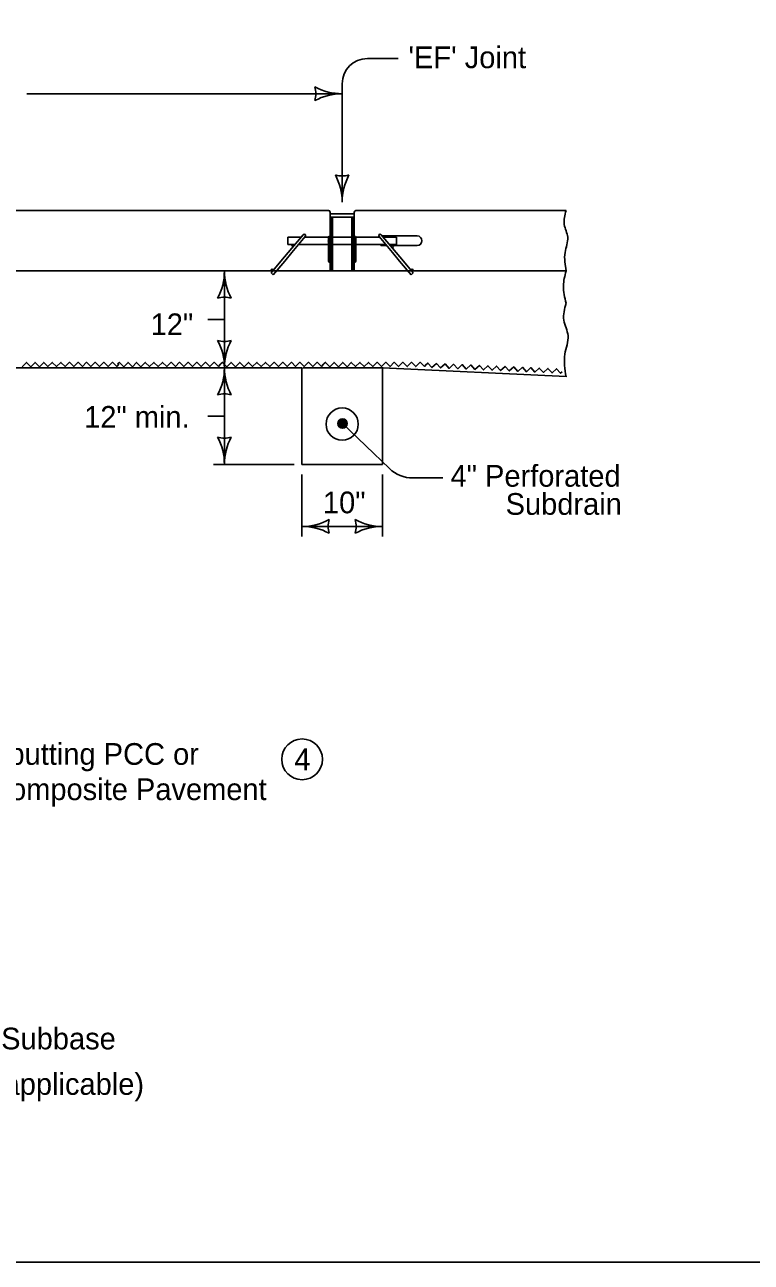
# Model space of a CAD drawing. Extents: x 5546 to 81668, y 3174 to 15999.
# Drawn here: x 15194 to 15729, y 7924 to 8836 of the extents above; entities that cross this region are included whole.
import ezdxf

# ---------------------------------------------------------------- set-up
doc = ezdxf.new("R2010")
doc.units = 0
for name, color, linetype in [('Level 61', 7, 'Continuous'), ('PS_BOLT', 7, 'Continuous'), ('PS_CONST', 7, 'Continuous'), ('PS_DAWA', 7, 'Continuous'), ('PS_DIM', 7, 'Continuous'), ('PS_SHAPE', 7, 'Continuous'), ('PS_TEXT', 7, 'Continuous')]:
    doc.layers.add(name, color=color, linetype=linetype)

msp = doc.modelspace()

# ---------------------------------------------------------------- linework, layer by layer
at = {"layer": 'Level 61'}
msp.add_lwpolyline([(13732.52, 9944.02), (16867.53, 9944.02), (16867.53, 7924.02), (13732.52, 7924.02)], close=True, dxfattribs=at)
at = {"layer": 'PS_BOLT'}
for p, q in [((15417.71, 8699.17), (14866.72, 8699.17)), ((15418.96, 8697.92), (15418.96, 8697.92)), ((15418.96, 8654.62), (15418.96, 8697.92)), ((14866.72, 8654.62), (15305.81, 8654.62)), ((15305.81, 8654.62), (15418.96, 8654.62))]:
    msp.add_line(p, q, dxfattribs=at)
msp.add_lwpolyline([(15418.96, 8697.92), (15418.62, 8698.92), (15417.71, 8699.17)], dxfattribs=at)
at = {"layer": 'PS_CONST'}
for p, q in [((15469.22, 8811.23), (15446.43, 8811.23)), ((15427.87, 8737.7), (15427.87, 8792.66)), ((15427.87, 8705.31), (15427.87, 8737.7)), ((15341.13, 8654.62), (15341.13, 8583.34)), ((15341.13, 8618.98), (15329.01, 8618.98)), ((15341.13, 8583.34), (15341.13, 8512.06)), ((15341.13, 8547.7), (15329.01, 8547.7)), ((15427.82, 8542.44), (15462.64, 8509.02)), ((15392.59, 8512.06), (15333.02, 8512.06)), ((15398.17, 8504.63), (15398.17, 8458.91)), ((15457.57, 8504.63), (15457.57, 8458.91)), ((15502.03, 8502.06), (15479.96, 8502.06)), ((15457.57, 8466.33), (15398.17, 8466.33))]:
    msp.add_line(p, q, dxfattribs=at)
msp.add_lwpolyline([(15428.45, 8538.98), (15427.28, 8539.51), (15425.46, 8540.07), (15425.11, 8541.91), (15425.36, 8543.53), (15426.52, 8545.03), (15428.25, 8544.88), (15430.08, 8544.62), (15430.95, 8543.17), (15431.11, 8541.64), (15430.03, 8539.63), (15428.7, 8539.46), (15426.88, 8539.93), (15425.39, 8541.09), (15425.44, 8542.82), (15426.6, 8544.21), (15428.24, 8544.37), (15430.06, 8544.01), (15430.33, 8542.98), (15430.71, 8541.75), (15429.85, 8540.24), (15428.52, 8540.28), (15427, 8540.53), (15425.91, 8541.38), (15426.46, 8542.89), (15427.61, 8543.78), (15429.14, 8543.83), (15429.52, 8543.01), (15430, 8542.08), (15429.26, 8540.88), (15428.12, 8540.6), (15427.12, 8541.14), (15427.05, 8542.26), (15427.59, 8543.06), (15428.62, 8543.34), (15429.11, 8542.92), (15429.4, 8542.29), (15428.86, 8541.4), (15428.14, 8541.21), (15427.44, 8541.64), (15427.56, 8542.25), (15428.08, 8542.64), (15428.8, 8542.62), (15428.78, 8542.11), (15428.16, 8541.82)], dxfattribs=at)
msp.add_circle((15428.18, 8542.16), 3.47, dxfattribs=at)
for centre, radius, start, end in [((15446.43, 8792.67), 18.56, 90, 180), ((15427.87, 8741.16), 16.51, 252.26665, 287.73335), ((15385.12, 8705.31), 42.75, 0, 28.07249), ((15470.62, 8705.31), 42.75, 151.92751, 180), ((15298.38, 8654.62), 42.75, 331.92751, 0), ((15383.88, 8654.62), 42.75, 180, 208.07249), ((15341.13, 8618.78), 16.51, 72.26665, 107.73335), ((15341.13, 8619.18), 16.51, 252.26665, 287.73335), ((15298.38, 8583.34), 42.75, 0, 28.07249), ((15383.88, 8583.34), 42.75, 151.92751, 180), ((15298.38, 8583.34), 42.75, 331.92751, 0), ((15383.88, 8583.34), 42.75, 180, 208.07249), ((15341.13, 8547.5), 16.51, 72.26665, 107.73335), ((15341.13, 8547.9), 16.51, 252.26665, 287.73335), ((15298.38, 8512.06), 42.75, 0, 28.07249), ((15383.88, 8512.06), 42.75, 151.92751, 180), ((15479.96, 8527.06), 25, 226.17392, 270), ((15398.17, 8509.08), 42.75, 270, 298.07249), ((15398.17, 8423.58), 42.75, 61.92751, 90), ((15434.01, 8466.33), 16.51, 162.26665, 197.73335), ((15421.73, 8466.33), 16.51, 342.26665, 17.73335), ((15457.57, 8509.08), 42.75, 241.92751, 270), ((15457.57, 8423.58), 42.75, 90, 118.07249)]:
    msp.add_arc(centre, radius, start, end, dxfattribs=at)
at = {"layer": 'PS_DAWA'}
msp.add_line((15427.87, 8785.23), (15195.61, 8785.23), dxfattribs=at)
for centre, radius, start, end in [((15392.02, 8785.24), 16.51, 342.26665, 17.73335), ((15427.87, 8827.99), 42.75, 241.92751, 270), ((15392.02, 8785.24), 16.51, 342.26665, 17.73335), ((15427.87, 8827.99), 42.75, 241.92751, 270), ((15427.87, 8742.49), 42.75, 90, 118.07249), ((15427.87, 8742.49), 42.75, 90, 118.07249)]:
    msp.add_arc(centre, radius, start, end, dxfattribs=at)
at = {"layer": 'PS_DIM'}
for p, q in [((15436.78, 8679.61), (15436.78, 8697.93)), ((15438.02, 8699.17), (15592.87, 8699.17)), ((15437.85, 8661.75), (15437.85, 8679.57)), ((15436.78, 8654.62), (15436.78, 8661.71)), ((15476.31, 8654.62), (15436.78, 8654.62)), ((15592.87, 8654.62), (15476.31, 8654.62))]:
    msp.add_line(p, q, dxfattribs=at)
for centre, radius, start, end in [((15438.02, 8697.93), 1.25, 90, 180), ((15437.31, 8679.57), 0.535, 0, 176.27485), ((15437.31, 8661.75), 0.535, 184.7481, 0)]:
    msp.add_arc(centre, radius, start, end, dxfattribs=at)
msp.add_spline([(15592.87, 8699.17), (15591.51, 8688.88), (15594.08, 8679.51), (15592.12, 8668.32), (15592.87, 8654.62)], degree=3, dxfattribs=at)
at = {"layer": 'PS_SHAPE'}
for p, q in [((15417.71, 8699.17), (14310.64, 8699.17)), ((15418.96, 8668.16), (15418.96, 8697.92)), ((15436.78, 8696.76), (15418.96, 8696.76)), ((15420.74, 8694.36), (15418.96, 8694.36)), ((15419.14, 8694.36), (15419.14, 8668.16)), ((15419.32, 8694.36), (15419.32, 8668.16)), ((15419.49, 8694.36), (15419.49, 8668.16)), ((15419.67, 8694.36), (15419.67, 8668.16)), ((15419.85, 8694.36), (15419.85, 8668.16)), ((15420.03, 8694.36), (15420.03, 8668.16)), ((15420.21, 8694.36), (15420.21, 8668.16)), ((15420.38, 8694.36), (15420.38, 8668.16)), ((15420.56, 8694.36), (15420.56, 8668.16)), ((15420.74, 8694.36), (15420.74, 8679.57)), ((15420.74, 8694.36), (15435, 8694.36)), ((15420.74, 8679.57), (15420.74, 8694.36)), ((15435, 8694.36), (15435, 8679.57)), ((15435, 8694.36), (15435, 8679.57)), ((15436.78, 8694.36), (15435, 8694.36)), ((15435.18, 8694.36), (15435.18, 8668.16)), ((15435.35, 8694.36), (15435.35, 8668.16)), ((15435.53, 8694.36), (15435.53, 8668.16)), ((15435.71, 8694.36), (15435.71, 8668.16)), ((15435.89, 8694.36), (15435.89, 8668.16)), ((15436.07, 8694.36), (15436.07, 8668.16)), ((15436.24, 8694.36), (15436.24, 8668.16)), ((15436.42, 8694.36), (15436.42, 8668.16)), ((15436.6, 8694.36), (15436.6, 8668.16)), ((15436.78, 8668.16), (15436.78, 8697.92)), ((15592.87, 8699.17), (15438.03, 8699.17)), ((15387.77, 8674.22), (15387.77, 8679.57)), ((15397.58, 8679.57), (15387.77, 8679.57)), ((15393.09, 8674.22), (15387.77, 8674.22)), ((15399.05, 8681.32), (15388.01, 8668.16)), ((15390.8, 8668.16), (15400.69, 8679.95)), ((15417.89, 8674.22), (15395.88, 8674.22)), ((15397.58, 8679.57), (15397.58, 8679.57)), ((15417.89, 8679.57), (15400.37, 8679.57)), ((15417.89, 8661.75), (15417.89, 8679.57)), ((15417.89, 8678.86), (15417.89, 8678.86)), ((15420.74, 8679.57), (15420.74, 8674.22)), ((15435, 8679.57), (15420.74, 8679.57)), ((15435, 8674.22), (15420.74, 8674.22)), ((15420.74, 8674.22), (15420.74, 8668.16)), ((15435, 8679.57), (15435, 8674.22)), ((15435, 8674.22), (15435, 8668.16)), ((15437.31, 8680.1), (15437.31, 8680.1)), ((15437.85, 8661.75), (15437.85, 8679.57)), ((15455.37, 8679.57), (15437.85, 8679.57)), ((15459.86, 8674.22), (15437.85, 8674.22)), ((15464.94, 8668.16), (15455.05, 8679.95)), ((15456.38, 8674.22), (15456.38, 8673.33)), ((15456.69, 8681.32), (15467.73, 8668.16)), ((15483.11, 8680.46), (15457.41, 8680.46)), ((15458.16, 8679.57), (15458.16, 8679.57)), ((15467.96, 8679.57), (15458.16, 8679.57)), ((15467.96, 8674.22), (15462.65, 8674.22)), ((15467.96, 8674.22), (15467.96, 8679.57)), ((15388.01, 8668.16), (15382.75, 8661.89)), ((15390.8, 8668.16), (15385.54, 8661.89)), ((15418.96, 8661.89), (15418.96, 8668.16)), ((15419.14, 8668.16), (15419.14, 8661.89)), ((15419.32, 8668.16), (15419.32, 8661.89)), ((15419.49, 8668.16), (15419.49, 8661.89)), ((15419.67, 8668.16), (15419.67, 8661.89)), ((15419.85, 8668.16), (15419.85, 8661.89)), ((15420.03, 8668.16), (15420.03, 8661.89)), ((15420.21, 8668.16), (15420.21, 8661.89)), ((15420.38, 8668.16), (15420.38, 8661.89)), ((15420.56, 8668.16), (15420.56, 8661.89)), ((15420.74, 8668.16), (15420.74, 8661.89)), ((15435, 8668.16), (15435, 8661.89)), ((15435.18, 8668.16), (15435.18, 8661.89)), ((15435.35, 8668.16), (15435.35, 8661.89)), ((15435.53, 8668.16), (15435.53, 8661.89)), ((15435.71, 8668.16), (15435.71, 8661.89)), ((15435.89, 8668.16), (15435.89, 8661.89)), ((15436.07, 8668.16), (15436.07, 8661.89)), ((15436.24, 8668.16), (15436.24, 8661.89)), ((15436.42, 8668.16), (15436.42, 8661.89)), ((15436.6, 8668.16), (15436.6, 8661.89)), ((15436.78, 8661.89), (15436.78, 8668.16)), ((15460.6, 8673.33), (15456.38, 8673.33)), ((15483.11, 8673.33), (15463.4, 8673.33)), ((15464.94, 8668.16), (15470.2, 8661.89)), ((15467.73, 8668.16), (15472.99, 8661.89)), ((15382.75, 8661.89), (15375.5, 8653.26)), ((15385.54, 8661.89), (15377.14, 8651.89)), ((15418.96, 8654.62), (15418.96, 8661.89)), ((15419.14, 8661.89), (15419.14, 8654.62)), ((15419.32, 8661.89), (15419.32, 8654.62)), ((15419.49, 8661.89), (15419.49, 8654.62)), ((15419.67, 8661.89), (15419.67, 8654.62)), ((15419.85, 8661.89), (15419.85, 8654.62)), ((15420.03, 8661.89), (15420.03, 8654.62)), ((15420.21, 8661.89), (15420.21, 8654.62)), ((15420.38, 8661.89), (15420.38, 8654.62)), ((15420.56, 8661.89), (15420.56, 8654.62)), ((15420.74, 8661.89), (15420.74, 8654.62)), ((15435, 8661.89), (15435, 8654.62)), ((15435.18, 8661.89), (15435.18, 8654.62)), ((15435.35, 8661.89), (15435.35, 8654.62)), ((15435.53, 8661.89), (15435.53, 8654.62)), ((15435.71, 8661.89), (15435.71, 8654.62)), ((15435.89, 8661.89), (15435.89, 8654.62)), ((15436.07, 8661.89), (15436.07, 8654.62)), ((15436.24, 8661.89), (15436.24, 8654.62)), ((15436.42, 8661.89), (15436.42, 8654.62)), ((15436.6, 8661.89), (15436.6, 8654.62)), ((15436.78, 8654.62), (15436.78, 8661.89)), ((15437.85, 8661.75), (15437.85, 8661.75)), ((15470.2, 8661.89), (15478.6, 8651.89)), ((15472.99, 8661.89), (15480.24, 8653.26)), ((15376.64, 8654.62), (14310.64, 8654.62)), ((15377.14, 8651.89), (15375.5, 8653.26)), ((15420.74, 8654.62), (15379.43, 8654.62)), ((15435, 8654.62), (15420.74, 8654.62)), ((15476.31, 8654.62), (15435, 8654.62)), ((15478.6, 8651.89), (15480.24, 8653.26)), ((15592.87, 8654.62), (15479.1, 8654.62)), ((15398.17, 8583.34), (14310.64, 8583.34)), ((15398.17, 8512.06), (15398.17, 8583.34)), ((15458.19, 8583.34), (15398.79, 8583.34)), ((15457.57, 8512.06), (15457.57, 8583.34)), ((15457.57, 8583.34), (15592.87, 8576.78)), ((15457.57, 8512.06), (15398.17, 8512.06))]:
    msp.add_line(p, q, dxfattribs=at)
for points in [[(15435, 8694.22), (15434.85, 8694.36)], [(15435, 8673.93), (15434.7, 8674.22)], [(15263.38, 8585.83), (15261.8, 8584.23), (15258.62, 8587.39), (15255.46, 8584.22), (15252.28, 8587.38), (15249.12, 8584.19), (15245.95, 8587.36), (15242.79, 8584.18), (15239.61, 8587.34), (15236.46, 8584.16), (15233.27, 8587.33), (15230.11, 8584.15), (15226.94, 8587.31), (15223.78, 8584.13), (15220.6, 8587.29), (15217.44, 8584.12), (15214.27, 8587.28), (15211.11, 8584.1), (15207.94, 8587.26), (15204.78, 8584.08), (15201.59, 8587.24), (15198.44, 8584.07), (15195.27, 8587.23), (15192.1, 8584.04)], [(15338.22, 8585.83), (15336.64, 8584.23), (15333.46, 8587.39), (15330.31, 8584.22), (15327.12, 8587.38), (15323.96, 8584.19), (15320.8, 8587.36), (15317.64, 8584.18), (15314.45, 8587.34), (15311.3, 8584.16), (15308.12, 8587.33), (15304.96, 8584.15), (15301.78, 8587.31), (15298.63, 8584.13), (15295.44, 8587.29), (15292.28, 8584.12), (15289.12, 8587.28), (15285.96, 8584.1), (15282.78, 8587.26), (15279.62, 8584.08), (15276.44, 8587.24), (15273.28, 8584.07), (15270.11, 8587.23), (15266.95, 8584.04), (15263.77, 8587.21), (15262.35, 8586.08)], [(15414.19, 8585.83), (15412.61, 8584.23), (15409.43, 8587.39), (15406.28, 8584.22), (15403.09, 8587.38), (15399.93, 8584.19), (15396.77, 8587.36), (15393.6, 8584.18), (15390.42, 8587.34), (15387.27, 8584.16), (15384.09, 8587.33), (15380.93, 8584.15), (15377.75, 8587.31), (15374.6, 8584.13), (15371.41, 8587.29), (15368.25, 8584.12), (15365.09, 8587.28), (15361.92, 8584.1), (15358.75, 8587.26), (15355.59, 8584.08), (15352.41, 8587.24), (15349.25, 8584.07), (15346.08, 8587.23), (15342.92, 8584.04), (15339.74, 8587.21), (15338.32, 8586.08)], [(15490.06, 8585.83), (15488.48, 8584.23), (15485.3, 8587.39), (15482.15, 8584.22), (15478.96, 8587.38), (15475.8, 8584.19), (15472.63, 8587.36), (15469.47, 8584.18), (15466.29, 8587.34), (15463.14, 8584.16), (15459.95, 8587.33), (15456.79, 8584.15), (15453.62, 8587.31), (15450.47, 8584.13), (15447.28, 8587.29), (15444.12, 8584.12), (15440.95, 8587.28), (15437.79, 8584.1), (15434.62, 8587.26), (15431.46, 8584.08), (15428.27, 8587.24), (15425.12, 8584.07), (15421.95, 8587.23), (15418.79, 8584.04), (15415.61, 8587.21), (15414.18, 8586.08)], [(15565.3, 8581.9), (15563.65, 8580.38), (15560.63, 8583.68), (15557.33, 8580.65), (15554.29, 8583.96), (15551, 8580.93), (15547.96, 8584.23), (15544.66, 8581.21), (15541.64, 8584.5), (15538.33, 8581.48), (15535.3, 8584.78), (15532.01, 8581.75), (15528.98, 8585.06), (15525.67, 8582.02), (15522.64, 8585.33), (15519.35, 8582.3), (15516.32, 8585.6), (15513.01, 8582.57), (15509.99, 8585.87), (15506.69, 8582.84), (15503.65, 8586.15), (15500.36, 8583.12), (15497.32, 8586.42), (15494.02, 8583.39), (15491, 8586.69), (15489.35, 8585.18)], [(15589.98, 8580.33), (15588.82, 8579.26), (15585.79, 8582.57), (15582.49, 8579.53), (15579.45, 8582.84), (15576.16, 8579.82), (15573.12, 8583.11), (15569.82, 8580.09), (15566.8, 8583.38), (15565.15, 8581.88)]]:
    msp.add_lwpolyline(points, dxfattribs=at)
for centre, radius in [((15391.56, 8673.51), 0.713), ((15464.92, 8672.62), 0.713), ((15376.31, 8655.33), 0.713), ((15479.43, 8655.33), 0.713), ((15427.87, 8541.76), 11.88)]:
    msp.add_circle(centre, radius, dxfattribs=at)
for centre, radius, start, end in [((15417.71, 8697.92), 1.25, 0, 90), ((15438.03, 8697.92), 1.25, 90, 180), ((15399.87, 8680.64), 1.07, 320.00367, 139.99636), ((15418.42, 8679.57), 0.535, 0, 180), ((15437.31, 8679.57), 0.535, 0, 180), ((15455.87, 8680.64), 1.07, 40.00364, 219.99633), ((15483.11, 8676.9), 3.56, 270, 90), ((15418.42, 8661.75), 0.535, 180, 0), ((15437.31, 8661.75), 0.535, 180, 0)]:
    msp.add_arc(centre, radius, start, end, dxfattribs=at)
for points in [[(15592.87, 8699.17), (15591.51, 8688.87), (15594.08, 8679.5), (15592.12, 8668.31), (15592.87, 8654.62)], [(15417.89, 8679.21), (15417.79, 8679.2), (15417.71, 8679.22), (15417.63, 8679.2), (15417.57, 8679.22), (15417.51, 8679.2), (15417.45, 8679.21)], [(15417.89, 8678.86), (15417.79, 8678.85), (15417.71, 8678.86), (15417.63, 8678.85), (15417.57, 8678.86), (15417.51, 8678.84), (15417.45, 8678.85)], [(15417.89, 8678.5), (15417.79, 8678.49), (15417.71, 8678.5), (15417.63, 8678.49), (15417.57, 8678.51), (15417.51, 8678.49), (15417.45, 8678.5)], [(15417.89, 8678.14), (15417.79, 8678.14), (15417.71, 8678.15), (15417.63, 8678.14), (15417.57, 8678.15), (15417.51, 8678.13), (15417.45, 8678.14)], [(15417.89, 8677.79), (15417.79, 8677.78), (15417.71, 8677.79), (15417.63, 8677.78), (15417.57, 8677.79), (15417.51, 8677.77), (15417.45, 8677.78)], [(15417.89, 8677.43), (15417.79, 8677.42), (15417.71, 8677.43), (15417.63, 8677.42), (15417.57, 8677.44), (15417.51, 8677.42), (15417.45, 8677.43)], [(15417.89, 8677.07), (15417.79, 8677.07), (15417.71, 8677.08), (15417.63, 8677.07), (15417.57, 8677.08), (15417.51, 8677.06), (15417.45, 8677.07)], [(15417.89, 8676.72), (15417.79, 8676.71), (15417.71, 8676.72), (15417.63, 8676.71), (15417.57, 8676.73), (15417.51, 8676.71), (15417.45, 8676.71)], [(15417.89, 8676.36), (15417.79, 8676.35), (15417.71, 8676.37), (15417.63, 8676.35), (15417.57, 8676.37), (15417.51, 8676.35), (15417.45, 8676.36)], [(15417.89, 8676), (15417.79, 8676), (15417.71, 8676.01), (15417.63, 8676), (15417.57, 8676.01), (15417.51, 8675.99), (15417.45, 8676)], [(15417.89, 8675.65), (15417.79, 8675.64), (15417.71, 8675.65), (15417.63, 8675.64), (15417.57, 8675.66), (15417.51, 8675.64), (15417.45, 8675.64)], [(15417.89, 8675.29), (15417.79, 8675.28), (15417.71, 8675.3), (15417.63, 8675.28), (15417.57, 8675.3), (15417.51, 8675.28), (15417.45, 8675.29)], [(15417.89, 8674.94), (15417.79, 8674.93), (15417.71, 8674.94), (15417.63, 8674.93), (15417.57, 8674.94), (15417.51, 8674.92), (15417.45, 8674.93)], [(15417.89, 8674.58), (15417.79, 8674.57), (15417.71, 8674.58), (15417.63, 8674.57), (15417.57, 8674.59), (15417.51, 8674.57), (15417.45, 8674.58)], [(15592.87, 8654.62), (15590.91, 8643.68), (15592.87, 8630.86)], [(15592.87, 8630.86), (15591.22, 8618.35), (15594.34, 8606.95), (15591.96, 8593.36), (15592.87, 8576.71)]]:
    msp.add_spline(points, degree=3, dxfattribs=at)
at = {"layer": 'PS_TEXT'}
msp.add_circle((15398.34, 8294.69), 15, dxfattribs=at)

# ---------------------------------------------------------------- texts
at = {"layer": 'PS_CONST'}
for s, p in [("'EF' Joint", (15476.73, 8804.1)), ('12"', (15286.75, 8607.32)), ('12" min.', (15237.74, 8539.07)), ('4" Perforated', (15507.7, 8495.62)), ('10"', (15413.71, 8476.04)), ('   Subdrain', (15530.47, 8474.91)), ('Abutting PCC or', (15167.71, 8290.64)), ('Composite Pavement', (15167.71, 8264.64)), ('Subbase', (15176.61, 8080.91)), ('(if applicable)', (15154.67, 8047.4))]:
    msp.add_text(s, height=16, dxfattribs=at).set_placement(p)
at = {"layer": 'PS_TEXT'}
msp.add_text('4', height=16, dxfattribs=at).set_placement((15392.67, 8286.69))

doc.saveas('drawing.dxf')
